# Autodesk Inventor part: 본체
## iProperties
Created: 2015-04
Part Number: 본체
Document SubType Name: Modeling
Designer: elite
Density: 2.71 g/cm^3
Material: 알루미늄-6061
Mass: 1064.42 g
Surface Area: 1062.34 cm^2
Volume: 392.774 cm^3
Author: elite
